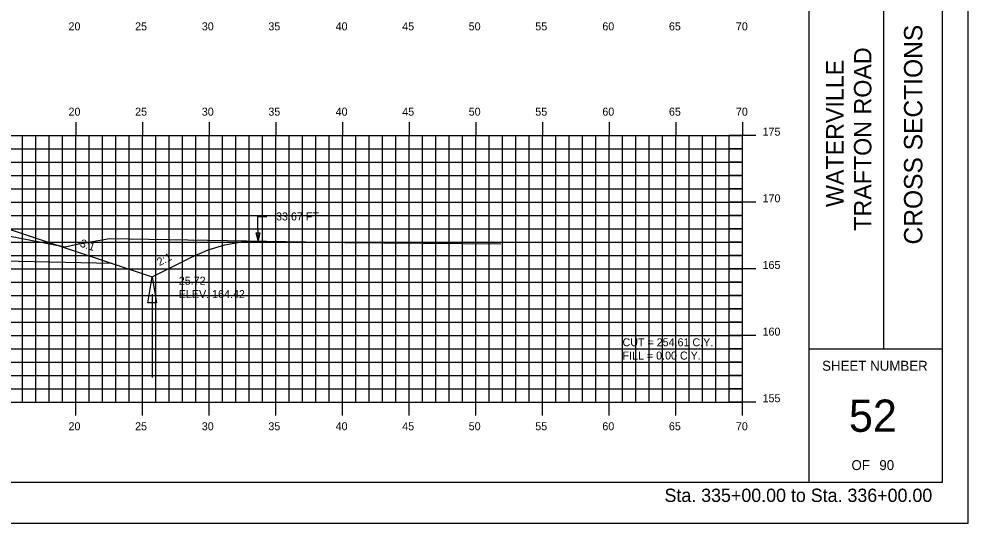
# Model space of a CAD drawing. Extents: x 1142089 to 1142259, y 608981 to 609091.
# Drawn here: x 1142188.3 to 1142259.4, y 608981.3 to 609019.1 of the extents above; entities that cross this region are included whole.
import ezdxf

# ---------------------------------------------------------------- set-up
doc = ezdxf.new("R2010")
doc.units = 0
for name, color, linetype in [('ANNOTATION', 7, 'Continuous'), ('BORDER', 7, 'Continuous'), ('D_Drainage_Ditch_Line', 7, 'Continuous'), ('D_Roadway_SlopeLines', 7, 'Continuous'), ('D_Roadway_SubGrade', 7, 'Continuous'), ('D_Text_Standard', 7, 'Continuous'), ('H_V ANNOTATION', 7, 'Continuous'), ('HIGHWAY_TITLE', 7, 'Continuous'), ('MAJOR', 7, 'Continuous'), ('MINOR', 7, 'Continuous'), ('PLOT BOUNDARY', 7, 'Continuous'), ('S_Roadway_Centerline', 7, 'Continuous')]:
    doc.layers.add(name, color=color, linetype=linetype)

msp = doc.modelspace()

# ---------------------------------------------------------------- linework, layer by layer
msp.add_lwpolyline([(1142136.678, 609003.566), (1142137.928, 609003.49), (1142139.178, 609003.257), (1142140.428, 609002.867), (1142141.678, 609002.32), (1142146.816, 608999.752), (1142149.816, 609000.752), (1142157.539, 609003.326), (1142157.54, 609003.326), (1142161.54, 609003.486), (1142172.54, 609003.706), (1142183.54, 609003.486), (1142187.54, 609003.326), (1142195.264, 609000.752), (1142198.264, 608999.752), (1142201.207, 609001.223), (1142202.457, 609001.767), (1142203.707, 609002.15), (1142204.957, 609002.371), (1142206.207, 609002.43)])
at = {"layer": 'BORDER'}
for p, q in [((1142247.541, 608984.335), (1142247.541, 609089.335)), ((1142253.132, 608994.338), (1142253.132, 609029.338)), ((1142247.541, 608994.338), (1142257.541, 608994.338))]:
    msp.add_line(p, q, dxfattribs=at)
msp.add_lwpolyline([(1142097.541, 608984.335), (1142257.541, 608984.335), (1142257.541, 609089.335), (1142097.541, 609089.335)], close=True, dxfattribs=at)
at = {"layer": 'D_Drainage_Ditch_Line'}
msp.add_line((1142198.264, 608998.439), (1142198.263, 608992.196), dxfattribs=at)
msp.add_lwpolyline([(1142198.592, 608997.783), (1142197.936, 608997.783), (1142198.264, 608999.752)], close=True, dxfattribs=at)
at = {"layer": 'D_Roadway_SlopeLines'}
for points in [[(1142198.264, 608999.752), (1142201.207, 609001.223), (1142202.457, 609001.767), (1142203.707, 609002.15), (1142204.957, 609002.371), (1142206.207, 609002.43)], [(1142195.264, 609000.752), (1142198.264, 608999.752)]]:
    msp.add_lwpolyline(points, dxfattribs=at)
at = {"layer": 'D_Roadway_SubGrade'}
msp.add_lwpolyline([(1142183.54, 609003.069), (1142183.54, 609003.236), (1142187.54, 609003.076), (1142187.54, 609003.326), (1142187.54, 609003.326), (1142195.264, 609000.752), (1142183.54, 609000.986)], close=True, dxfattribs=at)
at = {"layer": 'D_Text_Standard'}
msp.add_lwpolyline([(1142206.207, 609002.473), (1142206.195, 609004.275), (1142206.875, 609004.275)], dxfattribs=at)
msp.add_lwpolyline([(1142206.207, 609002.473), (1142206.058, 609003.054), (1142206.349, 609003.056)], close=True, dxfattribs=at)
at = {"layer": 'MAJOR'}
for p, q in [((1142192.54, 609011.337), (1142192.54, 609010.335)), ((1142197.54, 609011.337), (1142197.54, 609010.335)), ((1142202.54, 609011.337), (1142202.54, 609010.335)), ((1142207.54, 609011.337), (1142207.54, 609010.335)), ((1142212.54, 609011.337), (1142212.54, 609010.335)), ((1142217.54, 609011.337), (1142217.54, 609010.335)), ((1142222.54, 609011.337), (1142222.54, 609010.335)), ((1142227.54, 609011.337), (1142227.54, 609010.335)), ((1142232.54, 609011.337), (1142232.54, 609010.335)), ((1142237.54, 609011.337), (1142237.54, 609010.335)), ((1142242.54, 609011.337), (1142242.54, 609010.335)), ((1142102.54, 609010.335), (1142242.54, 609010.335)), ((1142102.54, 609010.335), (1142242.54, 609010.335)), ((1142192.54, 608990.335), (1142192.54, 609010.335)), ((1142197.54, 608990.335), (1142197.54, 609010.335)), ((1142202.54, 608990.335), (1142202.54, 609010.335)), ((1142207.54, 608990.335), (1142207.54, 609010.335)), ((1142212.54, 608990.335), (1142212.54, 609010.335)), ((1142217.54, 608990.335), (1142217.54, 609010.335)), ((1142222.54, 608990.335), (1142222.54, 609010.335)), ((1142227.54, 608990.335), (1142227.54, 609010.335)), ((1142232.54, 608990.335), (1142232.54, 609010.335)), ((1142237.54, 608990.335), (1142237.54, 609010.335)), ((1142243.542, 609010.335), (1142241.538, 609010.335)), ((1142242.54, 608990.335), (1142242.54, 609010.335)), ((1142242.54, 608990.335), (1142242.54, 609010.335)), ((1142102.54, 609005.335), (1142242.54, 609005.335)), ((1142243.542, 609005.335), (1142241.538, 609005.335)), ((1142102.54, 609000.335), (1142242.54, 609000.335)), ((1142243.542, 609000.335), (1142241.538, 609000.335)), ((1142102.54, 608995.335), (1142242.54, 608995.335)), ((1142243.542, 608995.335), (1142241.538, 608995.335)), ((1142102.54, 608990.335), (1142242.54, 608990.335)), ((1142102.54, 608990.335), (1142242.54, 608990.335)), ((1142192.54, 608989.333), (1142192.54, 608990.335)), ((1142197.54, 608989.333), (1142197.54, 608990.335)), ((1142202.54, 608989.333), (1142202.54, 608990.335)), ((1142207.54, 608989.333), (1142207.54, 608990.335)), ((1142212.54, 608989.333), (1142212.54, 608990.335)), ((1142217.54, 608989.333), (1142217.54, 608990.335)), ((1142222.54, 608989.333), (1142222.54, 608990.335)), ((1142227.54, 608989.333), (1142227.54, 608990.335)), ((1142232.54, 608989.333), (1142232.54, 608990.335)), ((1142237.54, 608989.333), (1142237.54, 608990.335)), ((1142243.542, 608990.335), (1142241.538, 608990.335)), ((1142242.54, 608989.333), (1142242.54, 608990.335))]:
    msp.add_line(p, q, dxfattribs=at)
at = {"layer": 'MINOR'}
for p, q in [((1142188.54, 608990.335), (1142188.54, 609010.335)), ((1142189.54, 608990.335), (1142189.54, 609010.335)), ((1142190.54, 608990.335), (1142190.54, 609010.335)), ((1142191.54, 608990.335), (1142191.54, 609010.335)), ((1142193.54, 608990.335), (1142193.54, 609010.335)), ((1142194.54, 608990.335), (1142194.54, 609010.335)), ((1142195.54, 608990.335), (1142195.54, 609010.335)), ((1142196.54, 608990.335), (1142196.54, 609010.335)), ((1142198.54, 608990.335), (1142198.54, 609010.335)), ((1142199.54, 608990.335), (1142199.54, 609010.335)), ((1142200.54, 608990.335), (1142200.54, 609010.335)), ((1142201.54, 608990.335), (1142201.54, 609010.335)), ((1142203.54, 608990.335), (1142203.54, 609010.335)), ((1142204.54, 608990.335), (1142204.54, 609010.335)), ((1142205.54, 608990.335), (1142205.54, 609010.335)), ((1142206.54, 608990.335), (1142206.54, 609010.335)), ((1142208.54, 608990.335), (1142208.54, 609010.335)), ((1142209.54, 608990.335), (1142209.54, 609010.335)), ((1142210.54, 608990.335), (1142210.54, 609010.335)), ((1142211.54, 608990.335), (1142211.54, 609010.335)), ((1142213.54, 608990.335), (1142213.54, 609010.335)), ((1142214.54, 608990.335), (1142214.54, 609010.335)), ((1142215.54, 608990.335), (1142215.54, 609010.335)), ((1142216.54, 608990.335), (1142216.54, 609010.335)), ((1142218.54, 608990.335), (1142218.54, 609010.335)), ((1142219.54, 608990.335), (1142219.54, 609010.335)), ((1142220.54, 608990.335), (1142220.54, 609010.335)), ((1142221.54, 608990.335), (1142221.54, 609010.335)), ((1142223.54, 608990.335), (1142223.54, 609010.335)), ((1142224.54, 608990.335), (1142224.54, 609010.335)), ((1142225.54, 608990.335), (1142225.54, 609010.335)), ((1142226.54, 608990.335), (1142226.54, 609010.335)), ((1142228.54, 608990.335), (1142228.54, 609010.335)), ((1142229.54, 608990.335), (1142229.54, 609010.335)), ((1142230.54, 608990.335), (1142230.54, 609010.335)), ((1142231.54, 608990.335), (1142231.54, 609010.335)), ((1142233.54, 608990.335), (1142233.54, 609010.335)), ((1142234.54, 608990.335), (1142234.54, 609010.335)), ((1142235.54, 608990.335), (1142235.54, 609010.335)), ((1142236.54, 608990.335), (1142236.54, 609010.335)), ((1142238.54, 608990.335), (1142238.54, 609010.335)), ((1142239.54, 608990.335), (1142239.54, 609010.335)), ((1142240.54, 608990.335), (1142240.54, 609010.335)), ((1142241.54, 608990.335), (1142241.54, 609010.335)), ((1142102.54, 609009.335), (1142242.54, 609009.335)), ((1142242.54, 609009.335), (1142241.538, 609009.335)), ((1142102.54, 609008.335), (1142242.54, 609008.335)), ((1142242.54, 609008.335), (1142241.538, 609008.335)), ((1142102.54, 609007.335), (1142242.54, 609007.335)), ((1142242.54, 609007.335), (1142241.538, 609007.335)), ((1142102.54, 609006.335), (1142242.54, 609006.335)), ((1142242.54, 609006.335), (1142241.538, 609006.335)), ((1142102.54, 609004.335), (1142242.54, 609004.335)), ((1142242.54, 609004.335), (1142241.538, 609004.335)), ((1142102.54, 609003.335), (1142242.54, 609003.335)), ((1142242.54, 609003.335), (1142241.538, 609003.335)), ((1142102.54, 609002.335), (1142242.54, 609002.335)), ((1142242.54, 609002.335), (1142241.538, 609002.335)), ((1142102.54, 609001.335), (1142242.54, 609001.335)), ((1142242.54, 609001.335), (1142241.538, 609001.335)), ((1142102.54, 608999.335), (1142242.54, 608999.335)), ((1142242.54, 608999.335), (1142241.538, 608999.335)), ((1142102.54, 608998.335), (1142242.54, 608998.335)), ((1142242.54, 608998.335), (1142241.538, 608998.335)), ((1142102.54, 608997.335), (1142242.54, 608997.335)), ((1142242.54, 608997.335), (1142241.538, 608997.335)), ((1142102.54, 608996.335), (1142242.54, 608996.335)), ((1142242.54, 608996.335), (1142241.538, 608996.335)), ((1142102.54, 608994.335), (1142242.54, 608994.335)), ((1142242.54, 608994.335), (1142241.538, 608994.335)), ((1142102.54, 608993.335), (1142242.54, 608993.335)), ((1142242.54, 608993.335), (1142241.538, 608993.335)), ((1142102.54, 608992.335), (1142242.54, 608992.335)), ((1142242.54, 608992.335), (1142241.538, 608992.335)), ((1142102.54, 608991.335), (1142242.54, 608991.335)), ((1142242.54, 608991.335), (1142241.538, 608991.335))]:
    msp.add_line(p, q, dxfattribs=at)
at = {"layer": 'PLOT BOUNDARY'}
msp.add_lwpolyline([(1142089.447, 608981.276), (1142259.447, 608981.276), (1142259.447, 609091.276), (1142089.447, 609091.276)], close=True, dxfattribs=at)
at = {"layer": 'S_Roadway_Centerline'}
msp.add_lwpolyline([(1142120.248, 609003.54), (1142140.088, 609003.572), (1142147.837, 609003.464), (1142152.153, 609002.5), (1142153.465, 609002.339), (1142154.47, 609002.585), (1142157.194, 609003.025), (1142158.087, 609003.093), (1142160.552, 609003.459), (1142163.514, 609003.498), (1142172.183, 609003.534), (1142180.268, 609003.447), (1142183.249, 609003.394), (1142185.379, 609003.23), (1142186.373, 609003.17), (1142186.402, 609003.118), (1142187.497, 609002.831), (1142191.74, 609001.996), (1142192.511, 609002.174), (1142195.062, 609002.623), (1142212.721, 609002.317), (1142224.423, 609002.225)], dxfattribs=at)

# ---------------------------------------------------------------- texts
at = {"layer": 'ANNOTATION'}
for s, rotation, p in [('-3:1', 341.56521, (1142192.552, 609002.11)), ('2:1', 26.56505, (1142198.808, 609000.542))]:
    msp.add_text(s, height=0.6, rotation=rotation, dxfattribs=at).set_placement(p)
at = {"layer": 'BORDER'}
msp.add_text('CROSS SECTIONS', height=1.37787, rotation=90, dxfattribs=at).set_placement((1142256.025, 609002.172))
for s, height, p in [('SHEET NUMBER', 0.74527, (1142248.506, 608992.701)), ('52', 2.4194, (1142250.516, 608988.118)), ('OF', 0.7453, (1142250.707, 608985.248)), ('90', 0.7453, (1142252.797, 608985.248))]:
    msp.add_text(s, height=height, dxfattribs=at).set_placement(p)
at = {"layer": 'D_Text_Standard'}
for s, p in [('33.67 FT', (1142207.555, 609003.975)), ('25.72', (1142200.264, 608999.152)), ('ELEV. 164.42', (1142200.264, 608998.15)), ('CUT = 254.61 C.Y.', (1142233.54, 608994.535)), ('FILL = 0.00 C.Y.', (1142233.54, 608993.539))]:
    msp.add_text(s, height=0.6, dxfattribs=at).set_placement(p)
at = {"layer": 'H_V ANNOTATION'}
for s, height, p in [('20', 0.6, (1142191.994, 609018.235)), ('25', 0.6, (1142196.986, 609018.235)), ('30', 0.6, (1142201.989, 609018.235)), ('35', 0.6, (1142206.981, 609018.235)), ('40', 0.6, (1142212.026, 609018.235)), ('45', 0.6, (1142217.018, 609018.235)), ('50', 0.6, (1142222.005, 609018.235)), ('55', 0.6, (1142226.997, 609018.235)), ('60', 0.6, (1142232.026, 609018.235)), ('65', 0.6, (1142237.018, 609018.235)), ('70', 0.6, (1142242.042, 609018.235)), ('20', 0.6, (1142191.994, 609011.835)), ('25', 0.6, (1142196.986, 609011.835)), ('30', 0.6, (1142201.989, 609011.835)), ('35', 0.6, (1142206.981, 609011.835)), ('40', 0.6, (1142212.026, 609011.835)), ('45', 0.6, (1142217.018, 609011.835)), ('50', 0.6, (1142222.005, 609011.835)), ('55', 0.6, (1142226.997, 609011.835)), ('60', 0.6, (1142232.026, 609011.835)), ('65', 0.6, (1142237.018, 609011.835)), ('70', 0.6, (1142242.042, 609011.835)), ('175', 0.6, (1142244.04, 609010.335)), ('170', 0.6, (1142244.04, 609005.335)), ('165', 0.6, (1142244.04, 609000.335)), ('160', 0.6, (1142244.04, 608995.335)), ('155', 0.6, (1142244.04, 608990.335)), ('20', 0.6, (1142191.994, 608988.235)), ('25', 0.6, (1142196.986, 608988.235)), ('30', 0.6, (1142201.989, 608988.235)), ('35', 0.6, (1142206.981, 608988.235)), ('40', 0.6, (1142212.026, 608988.235)), ('45', 0.6, (1142217.018, 608988.235)), ('50', 0.6, (1142222.005, 608988.235)), ('55', 0.6, (1142226.997, 608988.235)), ('60', 0.6, (1142232.026, 608988.235)), ('65', 0.6, (1142237.018, 608988.235)), ('70', 0.6, (1142242.042, 608988.235)), ('Sta. 335+00.00 to Sta. 336+00.00', 1.0002, (1142236.686, 608982.855))]:
    msp.add_text(s, height=height, dxfattribs=at).set_placement(p)
at = {"layer": 'HIGHWAY_TITLE'}
for s, height, p in [('TRAFTON ROAD', 1.30428, (1142252.2, 609003.201)), ('WATERVILLE', 1.3043, (1142250.113, 609004.98))]:
    msp.add_text(s, height=height, rotation=90, dxfattribs=at).set_placement(p)

doc.saveas('drawing.dxf')
